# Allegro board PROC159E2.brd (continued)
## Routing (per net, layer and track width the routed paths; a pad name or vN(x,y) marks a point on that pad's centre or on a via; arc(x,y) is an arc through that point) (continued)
OSPI_DQ5: length 22.5
  TOP w0.147: R456.2 v1(30.48,48.63)
  L03_SIG1 w0.091: v1(38.29,38.32) 38.96,39 38.96,43.12 38.96,43.97 38.61,44.32 37.87,44.32 37.43,43.87 36.38,43.87 35.43,44.82 31.49,44.82 30.48,45.84 30.48,46.77 30.56,46.85 30.85,46.85 30.93,46.93 30.93,47.04 30.85,47.12 30.56,47.12 30.48,47.2 30.48,47.32 30.56,47.4 30.85,47.4 30.93,47.48 30.93,47.59 30.85,47.67 30.56,47.67 30.48,47.75 v1(30.48,48.63)
  BOTTOM w0.147: v1(30.48,48.63) 30.63,48.63 30.65,48.61 R105.1 ; U80.26 v1(38.29,38.32)
OSPI_DQ6: length 22.5
  TOP w0.147: v1(33.93,49.36) 33.85,49.28 R457.2
  L03_SIG1 w0.091: v1(38.29,37.32) 39.24,38.27 39.24,42.55 39.24,44.08 38.73,44.59 38.5,44.59 37.76,44.59 37.6,44.43 37.39,44.22 36.49,44.22 34.23,46.49 34.23,48.25 34.1,48.37 33.93,48.37 33.81,48.25 33.81,47.08 33.68,46.95 33.5,46.95 33.38,47.06 33.38,48.81 v1(33.93,49.36)
  BOTTOM w0.147: v1(33.93,49.36) 33.93,49.31 33.99,49.25 R106.1 ; U80.24 v1(38.29,37.32)
OSPI_DQ7: length 23.3
  TOP w0.147: R458.2 v1(37.08,46.22)
  L03_SIG1 w0.091: v1(37.08,46.22) 37.08,46.59 37.06,46.6 37.06,48.41 37.15,48.5 37.28,48.5 37.39,48.4 37.39,46.8 37.6,46.59 37.75,46.59 37.83,46.67 37.83,48.45 37.91,48.53 38.03,48.53 38.11,48.45 38.11,46.68 38.2,46.59 38.73,46.59 39.79,45.52 39.79,44.72 39.51,44.44 39.51,37.55 v1(38.29,36.32)
  BOTTOM w0.147: v1(37.08,46.22) 37.06,46.2 R107.1 ; U80.22 v1(38.29,36.32)
OSPI_DQS_SOC: length 18.4
  L03_SIG1 w0.091: v1(30.26,43.16) 29.85,42.75 29.85,39.25 34.23,34.88 v1(40.73,34.88)
  BOTTOM w0.147: U80.20 v1(40.73,34.88) ; R112.2 v1(30.26,43.16)
OSPI_ERR#: length 43.9
  TOP w0.147: R3865.2 48.56,46.27 v1(48.52,46.32) ; U19.A5 R108.1 27.49,40.15 27.75,39.89 v1(28.01,39.89)
  L03_SIG1 w0.091: v1(48.52,46.32) 48.03,46.8 47.34,46.8 47.06,46.52 47.06,44.69 48.01,43.74 48.82,43.74 49.29,43.27 49.29,38.62 48.94,38.27 48.94,34.7 48.1,33.87 32.66,33.87 29.5,37.03 29.5,38.4 v1(28.01,39.89)
OSPI_LBCLK: length 22.2
  L03_SIG1 w0.091: v1(29.21,42.66) 28.82,42.27 28.82,39.62 33.99,34.45 41.3,34.45 v1(41.73,34.88)
  BOTTOM w0.147: R114.2 29.91,44.18 29.21,43.47 v1(29.21,42.66) ; U80.18 v1(41.73,34.88)
OSPI_RSTN: length 9.2
  TOP w0.147: U19.A4 30.85,39.31 30.98,39.18 v1(30.98,38.72)
  BOTTOM w0.147: U21.4 R121.1 35.68,38.2 35.16,38.72 v1(30.98,38.72)
PMIC_COMP1_IN+: length 45.9
  TOP w0.147: v1(109.12,34.27) 108.79,34.59 108.79,35.08 107.69,36.18 U7.21 ; v1(110.49,5.58) 110.92,5.14 110.92,4.36 110.44,3.88 J15.175
  L03_SIG1 w0.091: v1(110.49,5.58) 111.19,6.28 111.19,7.96 110.11,9.04 106.01,9.04 104.31,10.73 104.31,15.5 105.66,16.84 105.66,21.8 104.3,23.15 104.3,26.18 105.49,27.37 107.65,27.37 108.75,28.47 108.75,33.9 v1(109.12,34.27)
PMIC_COMP1_IN-: length 48.6
  TOP w0.147: v1(110.49,6.59) 111.24,5.84 J15.177 ; v1(110.89,34.34) 110.57,34.66 110.57,35.42 109.19,36.79 U7.24
  L03_SIG1 w0.091: v1(110.89,34.34) 110.41,34.82 109,34.82 108.51,34.33 108.51,28.71 107.53,27.73 105.45,27.73 103.86,26.14 103.86,23.07 105.47,21.46 105.47,18.31 104.02,16.86 104.02,10.66 106,8.68 110.09,8.68 110.93,7.84 110.93,7.04 v1(110.49,6.59)
PMIC_COMP2_IN+: length 56.7
  TOP w0.147: v1(108.23,47.1) 107.69,46.57 U7.28 ; J15.171 v1(108.84,4.56)
  L03_SIG1 w0.091: v1(108.84,4.56) 108.41,4.13 105.46,4.13 104.73,4.86 104.73,7 102.32,9.41 102.32,19.06 101.59,19.79 101.59,26.94 101.14,27.38 101.14,36.92 102.93,38.71 102.93,43.26 104.3,44.64 105.76,44.64 v1(108.23,47.1)
PMIC_COMP2_IN-: length 55.7
  TOP w0.147: v1(109.15,46.04) 109.19,45.99 U7.25 ; v1(110.49,7.61) 109.98,7.1 109.98,6.03 109.64,5.69 J15.173
  L03_SIG1 w0.091: v1(109.15,46.04) 106.99,43.89 106.99,38.83 106.4,38.24 104.51,38.24 102.86,36.59 102.86,35.13 101.81,34.08 101.81,28.46 103.53,26.74 103.53,22.85 104.5,21.88 104.5,18.02 103.75,17.27 103.75,10.58 105.97,8.36 109.74,8.36 v1(110.49,7.61)
PMIC_DIAG_OUT: length 79.1
  TOP w0.147: U1.V4 v1(55.38,32.83) ; U7.32 v1(105.69,46.09)
  L08_SIG2 w0.091: v1(100.32,25.79) 100.32,28.92 102.28,30.87 102.81,30.87 105.2,33.26 105.2,34.1 106.17,35.07 106.17,36.91 105.98,37.1 105.98,43.67 105.69,43.96 v1(105.69,46.09)
  BOTTOM w0.147: v1(100.32,25.79) 99.73,25.19 98.88,25.19 98.29,25.79 95.11,25.79 94.66,25.34 88.91,25.34 87.09,23.51 68.86,23.51 66.93,25.44 66.93,27.57 65.7,28.79 55.49,28.79 54.98,29.31 54.98,31.94 55.38,32.35 v1(55.38,32.83)
PMIC_EN_OUT: length 26.1
  TOP w0.147: U7.17 105.69,36.24 v1(105.74,36.19)
  L08_SIG2 w0.091: v1(105.74,36.19) 103.65,38.29 99.25,38.29 98.23,39.31 98.23,48.3 v1(97.62,48.91)
  BOTTOM w0.147: v1(97.62,48.91) 94.11,52.43 R51.1
PMIC_INTN: length 62.3
  TOP w0.147: U7.22 108.19,36.4 109.3,35.3 109.3,34.93 v1(109.92,34.3) ; U1.R17 v1(66.58,35.23)
  L03_SIG1 w0.091: v1(109.92,34.3) 109.03,33.4 109.03,28.37 107.35,26.69 v1(106.44,26.69)
  BOTTOM w0.114: v1(66.58,35.23) 66.18,34.83 66.18,33.36
  BOTTOM w0.147: v1(106.44,26.69) 88.18,26.69 87.75,26.25 68.22,26.25 67.49,26.99 67.49,28.63 66.18,29.93 66.18,33.36
PMIC_NRST: length 23.7
  TOP w0.147: U7.13 103.69,36.5 103.94,36.25 103.94,36.25 v1(104.26,35.93) ; v1(94.37,38.36) 93.54,37.53 84.93,37.53 84.05,36.65 R432.1
  L08_SIG2 w0.091: v1(104.26,35.93) 102.64,37.55 97.87,37.55 97.05,38.36 v1(94.37,38.36)
PMIC_SAFE_OUT1: length 109.2
  TOP w0.147: v1(66.24,6.59) 65.44,5.79 J15.113
  L08_SIG2 w0.091: v1(66.24,6.59) 66.84,6.59 69.11,8.86 69.11,12.12 70.33,13.34 90.56,13.34 90.99,12.91 90.99,12.39 94.5,8.88 94.5,6.17 95.61,5.06 104.4,5.06 105.93,3.53 108.92,3.53 109.64,4.25 109.64,8.09 108.22,9.51 108.22,10.02 107.19,11.05 104.76,11.05 104.28,11.53 104.28,15.36 103.91,15.74 103.91,17.49 104.53,18.12 104.53,24.11 104.06,24.58 104.06,25.85 105.8,27.59 105.8,30.46 108.44,33.09 108.44,35.76 109.79,37.11 v1(109.79,45.36)
  BOTTOM w0.147: v1(109.79,45.36) 109.24,45.36 108.81,44.94 R32.1
PMIC_SAFE_OUT2: length 80.4
  TOP w0.147: Q5.1 92.8,39.3 92.81,39.29 R202.1 94.07,39.96 95.78,41.67 95.78,46.58 97.24,48.04 97.67,48.04 98.51,48.88 v1(99.06,48.88) ; U7.27 v1(108.19,46.09)
  L03_SIG1 w0.091: v1(110.31,4.56) 109.76,5.11 109.76,5.37 109.05,6.08 105.36,6.08 105,6.44 105,7.03 102.56,9.46 102.56,18.73 102.8,18.97 102.8,20.84 103.06,21.1 103.06,26.75 101.44,28.37 101.44,36.35 103.89,38.8 103.89,43.21 104.94,44.26 106.36,44.26 v1(108.19,46.09)
  L08_SIG2 w0.091: v1(99.06,48.88) 101.53,48.88 102.25,48.16 106.77,48.16 107.62,47.31 107.62,46.66 v1(108.19,46.09)
  BOTTOM w0.147: v1(110.31,4.56) 110.63,4.24 110.86,4.24 111.24,3.86 J15.178
PMIC_SPI1_CLK: length 100.6
  TOP w0.147: v1(106.62,10.06) 106.09,9.53 105.48,9.53 105.13,9.88 102.87,9.88 102.5,9.51 95.12,9.51 92.52,12.11 90.2,12.11 89.86,12.46 89.86,13.12 88.94,14.04 65.18,14.04 64.51,14.71 62.35,14.71 60.61,12.97 U8.2 ; v1(104.77,47.1) 105.19,46.68 U7.33
  L08_SIG2 w0.091: v1(106.62,10.06) 106.09,10.59 104.62,10.59 103.77,11.44 103.77,12.29 100.56,15.5 100.56,23.83 103.59,26.86 103.59,29.61 107.3,33.32 107.3,34.62 107.67,34.99 107.67,38.27 108.01,38.61 108.01,44.31 106.69,45.63 106.69,47.02 106.12,47.59 105.26,47.59 v1(104.77,47.1)
  BOTTOM w0.147: R41.2 104.77,47.34 v1(104.77,47.1)
PMIC_SPI1_CS0: length 97
  TOP w0.147: v1(103.75,46.08) 103.69,46.03 U7.36 ; U8.14 61.26,16.06 62.1,15.23 64.64,15.23 65.51,14.36 89.16,14.36 90.11,13.4 91.79,13.4 95.32,9.87 102.3,9.87 102.8,10.38 105.39,10.38 v1(105.71,10.06)
  L08_SIG2 w0.091: v1(103.75,46.08) 104.24,46.58 105.87,46.58 106.27,46.17 106.27,44.95 107,44.22 107,38.58 107.36,38.22 107.36,35.39 106.18,34.21 106.18,32.62 103.4,29.84 102.8,29.84 102.14,29.18 102.14,26.05 100.38,24.29 100.38,15.3 103.5,12.18 103.5,11.3 104.48,10.32 105.45,10.32 v1(105.71,10.06)
  BOTTOM w0.147: v1(103.75,46.08) 103.3,46.08 102.99,46.39 R39.2
PMIC_SPI1_D0: length 113.3
  TOP w0.147: U7.35 104.19,45.92 104.22,45.94 104.22,46.64 v1(103.75,47.1) ; v1(107.72,54.19) TP17.1 109.08,54.19 109.11,54.22 R40.2 ; U8.5 62.56,13.53 63.27,14.24 64.38,14.24 64.89,13.73 88.69,13.73 89.5,12.92 89.5,12.28 90.02,11.75 92.37,11.75 94.99,9.13 102.71,9.13 103.1,9.52 104.88,9.52 105.29,9.12 106.6,9.12 v1(107.54,10.06)
  L03_SIG1 w0.091: v1(103.75,47.1) 104.52,47.87 104.52,49.1 107.72,52.31 v1(107.72,54.19)
  L08_SIG2 w0.091: v1(107.54,10.06) 106.76,10.83 104.63,10.83 104.05,11.42 104.05,12.39 100.74,15.69 100.74,23.57 104.76,27.59 104.76,30.41 107.21,32.86 107.75,32.86 108.23,33.34 108.23,36.99 109.4,38.16 109.4,43.9 107.07,46.23 107.07,47.17 106.37,47.87 104.52,47.87 v1(103.75,47.1)
PMIC_SPI1_D1: length 81.8
  TOP w0.147: v1(63.37,19.93) 63.37,19.47 63.21,19.31 U8.11
  L08_SIG2 w0.091: v1(109.35,55.35) 109.35,52.67 110.91,51.11 110.91,37.09 108.69,34.87 108.69,32.71 106.16,30.18 106.16,27.19 v1(104.86,25.88)
  BOTTOM w0.147: v1(109.35,55.35) R38.2 R142.2 ; v1(104.86,25.88) 101.26,25.88 100.14,24.76 98.59,24.76 98.03,25.32 95.72,25.32 94.78,24.38 88.81,24.38 87.5,23.08 67.69,23.08 65.55,20.94 64.38,20.94 v1(63.37,19.93)
PMIC_WKUP1: length 66.9
  TOP w0.147: v1(100.22,36.06) 100.19,36.08 U7.6
  L03_SIG1 w0.091: v1(66.24,7.61) 66.24,8.83 66.95,9.54 66.95,10.49 70.75,14.29 71.94,14.29 75.93,18.28 75.93,24.63 v1(74.81,25.76)
  L08_SIG2 w0.091: v1(100.22,36.06) 99.83,35.67 99.83,26.31 v1(99.31,25.79)
  BOTTOM w0.147: J15.114 65.44,6.81 v1(66.24,7.61) ; v1(74.81,25.76) 75.26,25.76 75.4,25.62 R34.2 76.88,24.91 77.64,25.67 88.37,25.67 88.94,26.23 98.86,26.23 v1(99.31,25.79)
PMIC_WKUP2: length 102.1
  TOP w0.147: v1(108.84,5.58) 109.39,6.13 109.39,7.89 108.03,9.26 108.03,10.23 107.4,10.86 94.87,10.86 91.98,13.75 90.31,13.75 89.34,14.72 79.65,14.72 75.91,18.46 J22.1 ; v1(98.67,47.87) 99.04,47.5 99.2,47.5 100.06,46.64 100.06,46.1 100.19,45.97 U7.43
  L03_SIG1 w0.091: v1(108.84,5.58) 109.26,5.15 109.26,4.38 108.83,3.95 105.38,3.95 104.55,4.79 104.55,6.93 102.13,9.34 102.13,18.88 101.34,19.68 101.34,26.74 100.73,27.35 100.73,36.65 99.9,37.48 99.9,46.64 v1(98.67,47.87)
  BOTTOM w0.147: v1(108.84,5.58) 108.38,5.12 108.38,4.37 108.84,3.92 J15.172
PORZ: length 259.1
  TOP w0.147: R419.1 67.93,11.93 v1(67.81,12.05) ; U36.2 v1(80.76,39.79) ; v1(86.22,36.38) 86.9,35.71 86.9,33.83 86.62,33.55 86.62,29.22 86.39,28.99 U79.4 84.79,28.3 TP75.1 v1(82.09,26.84) 81.12,25.87 75.79,25.87 73.3,23.37 67.11,23.37 66.56,22.83 62.05,22.83 61.25,22.02 50.98,22.02 47.56,25.44 41.12,25.44 40.3,26.25 39.32,26.25 38.37,27.2 38.37,31.12 v1(37.19,32.3) 35.52,33.97 27.87,33.97 26.8,32.9 24.39,32.9 21.91,35.37 21.91,52.66 25.77,56.51 25.77,60.89 27.7,62.82 27.7,63.65 26.9,64.45 26.9,66.67 28.66,68.43 41.14,68.43 45.95,73.24 45.95,74.38 46.62,75.05 46.62,77.77 45.75,78.64 45.75,85.2 48.86,88.3 51.67,88.3 53.96,90.6 55.11,90.6 56.69,92.18 v1(57.4,92.18) 57.4,91.1 58.2,90.3 61.94,90.3 63.55,91.91 67.18,91.91 67.54,92.26 67.54,99.86 v1(68,100.32) ; U1.R2 v1(53.78,35.23)
  L08_SIG2 w0.091: v1(37.19,32.3) 40.77,32.3 41.81,33.34 48.54,33.34 49.9,34.7 52.64,34.7 53.17,35.23 v1(53.78,35.23) ; v1(82.09,26.84) 82.09,20.03 76.06,14 69.76,14 v1(67.81,12.05)
  BOTTOM w0.147: U21.2 32.61,36.27 32.98,35.9 32.98,34.67 33.38,34.26 36.3,34.26 37.19,33.38 v1(37.19,32.3) ; R187.1 52.92,34.25 53.4,34.72 53.4,34.85 v1(53.78,35.23) ; v1(86.22,36.38) 82.11,36.38 81.21,35.48 80.59,35.48 80.05,36.01 80.05,39.08 v1(80.76,39.79) ; R327.1 v1(57.4,92.18) ; v1(68,100.32) U39.2
PORZ_RST: length 159
  TOP w0.147: U78.3 v1(80.19,32.03)
  L03_SIG1 w0.091: v1(52.9,98.23) 57.06,102.39 67.17,102.39 67.89,103.11 70.47,103.11 71.4,102.18 75.29,102.18 81.23,108.12 100.4,108.12 104.95,103.58 v1(104.95,97.59)
  L08_SIG2 w0.091: v1(96.61,48.91) 95.56,49.96 95.56,65.63 94.82,66.37 94.82,72.52 90.72,76.63 90.72,77.55 90.99,77.82 91.94,77.82 92.27,77.49 99.94,77.49 105.78,83.33 105.78,96.75 v1(104.95,97.59)
  BOTTOM w0.147: v1(96.61,48.91) 86.81,39.11 86.81,36.2 86.44,35.84 83.08,35.84 82.03,34.79 82.03,32.95 81.11,32.03 v1(80.19,32.03) ; v1(52.9,98.23) R427.2 52.9,95.25 53.06,95.09 U76.7
PORZ_VMAIN: length 1.8
  TOP w0.147: U78.4 U79.1
PR0_IEP0_EDC_SYNC_OUT0: length 2
  TOP w0.147: R420.1 J16.1
PR0_IEP0_EDC_SYNC_OUT1: length 10.4
  TOP w0.147: J18.1 64.28,54.88 64.28,53.79 63.82,53.34 R422.1
PR0_IEP0_EDIO_DATA_IN_OUT30: length 12.5
  BOTTOM w0.147: J17.1 62.08,63.67 62.08,56.52 63.68,54.92 R421.1
PR0_IEP0_EDIO_DATA_IN_OUT31: length 2.4
  TOP w0.147: J19.1 67.96,18.09 68.45,17.61 R423.1
PR0_MDIO0_MDC: length 21.2
  TOP w0.147: v1(74.47,36.71) 73.96,37.22 R211.2 ; R470.2 v1(77.35,29.38)
  L03_SIG1 w0.091: v1(77.35,29.38) 76.64,30.09 76.64,36.27 74.72,38.2 74.25,38.2 73.86,37.81 73.86,37.31 v1(74.47,36.71)
  BOTTOM w0.147: U90.2 77.9,37.43 77.5,37.83 75.59,37.83 v1(74.47,36.71) ; R470.2 v1(77.35,29.38)
PR0_MDIO0_MDC_ADD: length 87.7
  TOP w0.147: v1(71.53,91.19) 71.79,91.44 J8.20
  L08_SIG2 w0.091: v1(71.53,91.19) 71.53,86.48 70.3,85.25 70.3,84.71 69.93,84.34 68.38,84.34 67.43,83.4 67.43,80.65 v1(68.28,79.8)
  BOTTOM w0.147: v1(68.28,79.8) 67.81,79.32 65.42,79.32 64.64,80.11 63.8,80.11 62.45,78.75 62.45,72.01 60.9,70.46 60.9,67.65 61.6,66.95 64.98,66.95 65.35,66.58 65.35,64.17 63.32,62.14 63.32,57.15 68.02,52.45 71.09,52.45 72.03,51.52 72.03,49.78 71.78,49.53 71.78,48.12 71.96,47.95 72.29,47.62 74.39,47.62 74.85,47.16 76.07,47.16 76.59,46.64 76.59,45.55 75.75,44.7 75.75,41.18 73.39,38.82 73.39,34.96 74.23,34.12 75.1,34.12 75.37,34.4 R3867.2 76.77,34.96 76.9,35.09 U90.4
PR0_MDIO0_MDC_ON: length 62.9
  L08_SIG2 w0.091: v1(86.22,35.29) 90.53,39.6 90.53,47.64 92.47,49.58 92.47,57.71 93.06,58.3 93.06,62.31 91.35,64.02 91.35,73.72 89.92,75.15 v1(89.53,75.15)
  BOTTOM w0.147: U35.42 88.92,73.64 89.53,74.25 v1(89.53,75.15) ; U81.4 77.14,28.38 77.7,28.94 R472.2 83.76,28.94 85.41,30.6 85.41,33.72 85.7,34 85.7,34.76 v1(86.22,35.29)
PR0_MDIO0_MDIO: length 20.9
  TOP w0.147: R208.2 v1(74.47,34.7) ; v1(70.59,28.88) 71.34,28.88 71.74,28.48 R471.2
  L03_SIG1 w0.091: v1(74.47,34.7) 74.91,34.26 74.91,32.68 73.51,31.28 72.98,31.28 v1(70.59,28.88)
  BOTTOM w0.147: U90.8 77.4,38.96 76.84,38.4 74.45,38.4 73.81,37.76 73.81,35.36 v1(74.47,34.7) ; U81.8 v1(70.59,28.88)
PR0_MDIO0_MDIO_ADD: length 78.2
  TOP w0.147: J8.22 v1(73.27,91.84)
  L08_SIG2 w0.091: v1(68.28,78.89) 68.73,79.34 68.73,79.99 67.63,81.09 67.63,83.32 68.33,84.02 70.9,84.02 71.96,85.08 71.96,90.53 v1(73.27,91.84)
  BOTTOM w0.147: U90.6 R3866.2 76.99,42.07 77.19,42.26 77.19,46.46 76.19,47.45 74.98,47.45 74.52,47.91 72.41,47.91 72.2,48.12 72.2,49.47 72.32,49.59 72.32,51.64 71.21,52.75 68.14,52.75 63.61,57.27 63.61,62.02 65.65,64.05 65.65,66.7 65.1,67.25 61.72,67.25 61.2,67.77 61.2,70.34 62.74,71.89 62.74,78.63 63.79,79.68 64.51,79.68 65.3,78.89 v1(68.28,78.89)
PR0_MDIO0_MDIO_ON: length 75
  L08_SIG2 w0.091: v1(86.22,34.32) 85.78,34.77 85.78,36.92 90.29,41.43 90.29,47.75 92.22,49.68 92.22,57.81 92.81,58.4 92.81,61.19 90.31,63.69 90.31,65.16 90.93,65.79 90.93,73.5 90.16,74.28 89.63,74.28 v1(88.36,73.01)
  BOTTOM w0.147: v1(86.22,34.32) 86.78,34.32 87.7,33.4 87.7,29.11 86.39,27.79 78.54,27.79 77.47,26.72 70.33,26.72 70.15,26.9 R473.2 70.55,27.88 U81.6 ; v1(88.36,73.01) 88.42,72.95 U35.41
PR0_PRU0_GPIO0: length 35.3
  TOP w0.147: U87.2 v1(79.01,56.89) ; U1.K17 v1(66.58,39.23)
  L03_SIG1 w0.091: v1(66.58,39.23) 67.03,38.78 69.26,38.78 69.63,39.16 72.65,39.16 73.18,39.69 73.83,39.69 79.68,45.54 79.68,50.46 80.93,51.71 80.93,58.12 80.67,58.38 80.37,58.38 80.22,58.24 80.22,57.69 80.12,57.59 79.83,57.59 79.72,57.7 79.72,58.25 79.59,58.38 79.17,58.38 79.01,58.23 v1(79.01,56.89)
PR0_PRU0_GPIO1: length 35.2
  TOP w0.147: U87.3 79.2,57.39 79.74,56.86 v1(79.74,56.45) ; U1.K18 v1(67.38,39.23)
  L03_SIG1 w0.091: v1(79.74,56.45) 80.58,55.61 80.58,51.75 79.41,50.57 79.41,45.88 78.75,45.22 78.6,45.22 78.31,45.51 78.16,45.51 78.05,45.4 78.05,45.25 78.34,44.96 78.34,44.81 78.23,44.71 78.08,44.71 77.79,44.99 77.64,44.99 77.54,44.88 77.54,44.73 77.82,44.45 77.82,44.29 77.71,44.19 77.56,44.19 77.28,44.47 77.12,44.47 77.02,44.36 77.02,44.21 77.3,43.93 77.3,43.78 76.46,42.93 76.31,42.93 76.13,43.11 75.98,43.11 75.88,43 75.88,42.85 76.05,42.68 76.05,42.52 75.94,42.42 75.79,42.42 75.62,42.59 75.46,42.59 75.36,42.48 75.36,42.33 75.53,42.16 75.53,42.01 75.42,41.9 75.27,41.9 75.1,42.07 74.95,42.07 74.84,41.97 74.84,41.81 75.01,41.64 75.01,41.49 74.91,41.38 74.75,41.38 74.58,41.56 74.43,41.56 74.32,41.45 74.32,41.3 74.5,41.12 74.5,40.97 74.39,40.87 74.24,40.87 74.06,41.04 73.91,41.04 73.81,40.93 73.81,40.78 73.98,40.61 73.98,40.45 73.71,40.18 70.12,40.18 69.17,39.23 v1(67.38,39.23)
PR0_PRU0_GPIO2: length 35.3
  TOP w0.147: U1.J18 v1(67.38,40.83) ; v1(79.27,54.97) 80.19,55.9 80.19,57 79.3,57.89 U87.4
  L03_SIG1 w0.091: v1(79.27,54.97) 78.3,54.01 78.3,53.58 78.19,53.47 77.44,53.47 77.33,53.36 77.33,53.21 77.43,53.1 78.19,53.1 78.3,53 78.3,52.84 78.19,52.74 77.44,52.74 77.33,52.63 77.33,52.48 77.43,52.37 78.19,52.37 78.53,52.03 78.53,49.29 78.02,48.78 77.44,48.78 77.2,49.02 77.2,50.89 77,51.09 76.71,51.09 76.47,50.85 76.47,47.84 75.62,46.98 75.47,46.98 75.19,47.26 75.04,47.26 74.93,47.15 74.93,47 75.21,46.73 75.21,46.57 74.45,45.82 73.86,45.82 68.87,40.83 v1(67.38,40.83)
PR0_PRU0_GPIO3: length 35.1
  TOP w0.147: v1(78.14,55.11) 78.79,54.46 79.4,54.46 80.52,55.57 80.52,57.56 79.69,58.39 U87.5 ; U1.J17 v1(66.58,40.83)
  L03_SIG1 w0.091: v1(66.58,40.83) 66.81,40.83 67.2,41.22 67.52,41.22 69.94,43.63 70.4,43.63 73.03,46.26 74.11,46.26 74.58,46.73 74.58,47.84 74.86,48.13 74.86,48.28 74.48,48.66 74.48,48.81 74.58,48.92 74.74,48.92 75.12,48.54 75.27,48.54 75.38,48.64 75.38,48.79 74.99,49.18 74.99,49.33 75.1,49.44 75.25,49.44 75.63,49.05 75.79,49.05 76.09,49.36 76.09,49.9 75.99,50.01 75.58,50.01 75.47,50.12 75.47,50.27 75.58,50.38 75.99,50.38 76.09,50.48 76.09,51.47 75.99,51.58 75.42,51.58 75.31,51.68 75.31,51.84 75.42,51.94 75.99,51.94 76.09,52.05 76.09,52.2 75.99,52.31 75.42,52.31 75.31,52.42 75.31,52.57 75.42,52.67 75.99,52.67 76.09,52.78 76.09,53.6 77.6,55.11 v1(78.14,55.11)
PR0_PRU0_GPIO4: length 35.2
  TOP w0.147: U87.6 v1(79.01,58.89) ; U1.K16 v1(65.78,39.23)
  L03_SIG1 w0.091: v1(65.78,39.23) 66.28,39.73 67.76,39.73 68.19,40.16 69.28,40.16 72.84,43.72 75.03,43.72 75.33,44.02 75.33,44.17 75.17,44.33 75.17,44.48 75.28,44.59 75.43,44.59 75.59,44.43 75.74,44.43 75.85,44.54 75.85,44.69 75.69,44.84 75.69,45 75.8,45.1 75.95,45.1 76.1,44.95 76.26,44.95 76.36,45.06 76.36,45.21 76.21,45.36 76.21,45.51 76.32,45.62 76.47,45.62 76.62,45.47 76.77,45.47 76.88,45.57 76.88,45.72 76.73,45.88 76.73,46.03 76.83,46.14 76.99,46.14 77.14,45.98 77.29,45.98 77.4,46.09 77.4,46.24 77.24,46.4 77.24,46.55 77.35,46.65 77.5,46.65 77.66,46.5 77.81,46.5 77.92,46.61 77.92,46.76 77.76,46.91 77.76,47.06 77.87,47.17 78.02,47.17 78.17,47.02 78.33,47.02 78.43,47.12 78.43,47.28 78.28,47.43 78.28,47.58 78.39,47.69 78.54,47.69 78.69,47.53 78.84,47.53 79.13,47.82 79.13,50.69 80.31,51.87 80.31,55.26 79.15,56.41 78.84,56.41 78.57,56.68 78.57,58.45 v1(79.01,58.89)
PR0_PRU0_GPIO5: length 35.6
  TOP w0.147: v1(79.93,58.89) 79.43,59.39 U87.7 ; U1.G17 v1(66.58,42.43)
  L03_SIG1 w0.091: v1(79.93,58.89) 80.57,59.54 80.57,61.17 80.36,61.38 80.36,62.14 80.12,62.38 79.8,62.38 79.44,62.74 79.44,63.16 79.22,63.38 78.81,63.38 78.45,63.02 78.45,62.78 77.83,62.15 77.83,60.19 77.4,59.76 75.49,59.76 75.21,59.48 75.21,54.52 73.48,52.79 73.48,50.83 71.4,48.75 71.4,47.25 v1(66.58,42.43)
PR0_PRU0_GPIO6: length 35.5
  TOP w0.147: v1(79.93,61.89) 79.43,61.39 U87.11 ; U1.K15 v1(64.98,39.23)
  L03_SIG1 w0.091: v1(79.93,61.89) 79.46,61.42 79.46,60.4 78.85,59.8 78.85,59.35 78.3,58.8 78.3,55.94 78.8,55.44 79.47,55.44 79.74,55.17 79.74,51.68 78.86,50.8 78.86,48.85 74,43.99 72.65,43.99 69.1,40.44 68.08,40.44 67.64,40 65.75,40 v1(64.98,39.23)
PR0_PRU0_GPIO8: length 35.1
  TOP w0.147: U1.G15 v1(64.98,42.43) ; U87.12 v1(79.01,61.89)
  L03_SIG1 w0.091: v1(64.98,42.43) 65.38,42.83 65.96,42.83 66.19,42.59 66.19,42.25 66.42,42.02 67.57,42.02 69.77,44.21 70.49,44.21 71.04,44.76 71.04,44.92 70.66,45.3 70.66,45.45 70.77,45.56 70.92,45.56 71.3,45.17 71.45,45.17 71.56,45.28 71.56,45.43 71.18,45.82 71.18,45.97 71.28,46.08 71.43,46.08 71.82,45.69 71.97,45.69 72.08,45.8 72.08,45.95 71.69,46.34 71.69,46.49 71.8,46.6 71.95,46.6 72.34,46.21 72.49,46.21 72.6,46.32 72.6,46.47 72.21,46.85 72.21,47.01 72.32,47.11 72.47,47.11 72.86,46.73 73.01,46.73 73.7,47.42 73.7,47.86 73.32,48.23 73.32,49.19 74.89,50.76 74.89,52.81 78.02,55.94 78.02,58.99 78.51,59.47 78.51,61.39 v1(79.01,61.89)
PR0_PRU0_GPIO9: length 30.9
  TOP w0.147: U1.F17 v1(66.58,43.23) ; v1(79.93,62.89) 79.43,62.39 U87.13
  L03_SIG1 w0.091: v1(66.58,43.23) 68.78,45.43 68.78,47.81 72.1,51.13 72.1,52.01 74.93,54.84 74.93,61.64 75.41,62.11 77.36,62.11 78.03,62.78 78.03,62.99 78.7,63.66 79.54,63.66 79.93,63.27 v1(79.93,62.89)
PR0_PRU0_GPIO10: length 26.7
  TOP w0.147: U1.G18 v1(67.38,42.43) ; U87.14 v1(79.01,62.89)
  L03_SIG1 w0.091: v1(79.01,62.89) 78.17,62.05 78.17,59.92 77.75,59.51 77.75,56.33 73.93,52.51 73.93,50.7 71.75,48.52 71.75,47.17 67.38,42.8 v1(67.38,42.43)
PR0_PRU0_GPIO11: length 79.9
  TOP w0.147: U1.M16 v1(65.78,37.63)
  L03_SIG1 w0.091: v1(80.39,99.84) 79.96,99.84 77.32,97.19 77.32,80.14 73.1,75.92 73.1,74.03 69.23,70.16 66.4,70.16 62.4,66.16 62.4,63.28 61.63,62.51 61.63,53.64 60.86,52.87 60.86,47.29 60.58,47.01 60.58,40.46 61.35,39.69 62.76,39.69 62.97,39.48 62.97,37.42 63.16,37.23 65.38,37.23 v1(65.78,37.63)
  BOTTOM w0.147: U88.4 80.89,99.34 v1(80.39,99.84)
PR0_PRU0_GPIO12: length 79.7
  TOP w0.147: U1.M15 v1(64.98,37.63)
  L03_SIG1 w0.091: v1(64.98,37.63) 64.58,38.03 64.03,38.03 63.79,38.27 63.79,39.43 63.31,39.92 62.08,39.92 61.38,40.62 61.38,48.94 62.74,50.3 62.74,50.45 62.54,50.65 62.54,50.8 62.65,50.91 62.8,50.91 63,50.71 63.15,50.71 63.26,50.82 63.26,50.97 63.06,51.17 63.06,51.32 63.17,51.43 63.32,51.43 63.52,51.23 63.67,51.23 64.02,51.58 64.02,52.4 61.91,54.52 61.91,62.4 62.67,63.16 62.67,66.05 66.51,69.88 69.28,69.88 73.37,73.97 73.37,75.84 77.59,80.06 77.59,96.84 80.09,99.34 80.81,99.34 v1(81.3,99.84)
  BOTTOM w0.147: U88.5 v1(81.3,99.84)
PR0_PRU0_GPIO13: length 80
  TOP w0.147: U1.H17 v1(66.58,41.63)
  L03_SIG1 w0.091: v1(66.58,41.63) 66.41,41.63 66.02,41.24 64.02,41.24 63.78,41.48 63.78,47.64 64.41,48.27 66.4,48.27 66.89,48.75 66.89,52.04 62.71,56.21 62.71,61.46 65.46,64.21 65.46,64.97 74.1,73.61 74.1,75.37 75.35,76.62 76.62,76.62 77.19,77.18 78.57,77.18 78.69,77.31 78.69,93.33 80.04,94.68 80.04,96.58 80.65,97.19 81.34,97.19 81.94,97.78 81.94,99.89 81.48,100.34 80.88,100.34 v1(80.39,100.84)
  BOTTOM w0.147: v1(80.39,100.84) 80.89,100.34 U88.6
PR0_PRU0_GPIO14: length 80.3
  TOP w0.147: U1.H16 v1(65.78,41.63)
  L03_SIG1 w0.091: v1(65.78,41.63) 65.39,42.02 64.84,42.02 64.59,42.27 64.59,47.57 64.93,47.9 65.96,47.9 66.28,47.58 66.28,45.68 66.43,45.53 66.64,45.53 66.78,45.67 66.78,47.48 67.18,47.87 67.18,52.16 63,56.33 63,61.36 65.74,64.1 65.74,64.86 74.31,73.43 74.31,75.13 75.39,76.21 78.53,76.21 78.92,76.61 78.92,93.11 80.34,94.53 80.34,96.18 81.03,96.87 81.41,96.87 82.21,97.67 82.21,100.3 81.67,100.84 v1(81.3,100.84)
  BOTTOM w0.147: U88.7 v1(81.3,100.84)
PR0_PRU0_GPIO15: length 79.9
  TOP w0.147: U1.L16 v1(65.78,38.43)
  L03_SIG1 w0.091: v1(65.78,38.43) 65.39,38.82 64.79,38.82 64.59,39.02 64.59,39.67 64.05,40.21 62.57,40.21 62.18,40.6 62.18,48.14 62.45,48.42 62.45,48.57 62.1,48.92 62.1,49.08 62.2,49.18 62.36,49.18 62.71,48.83 62.86,48.83 62.97,48.93 62.97,49.08 62.61,49.44 62.61,49.59 62.72,49.7 62.87,49.7 63.23,49.34 63.38,49.34 63.49,49.45 63.49,49.6 63.13,49.96 63.13,50.11 63.24,50.22 63.39,50.22 63.75,49.86 63.9,49.86 64.01,49.97 64.01,50.12 63.65,50.48 63.65,50.63 63.76,50.73 63.91,50.73 64.26,50.38 64.42,50.38 64.58,50.54 64.58,52.23 62.18,54.63 62.18,61.68 64.93,64.43 64.93,65.19 73.61,73.88 73.61,75.66 78.15,80.2 78.15,93.78 79.26,94.89 79.26,97.71 v1(80.39,98.84)
  BOTTOM w0.147: U88.2 80.89,98.34 v1(80.39,98.84)
PR0_PRU0_GPIO16: length 79.7
  TOP w0.147: U1.H18 v1(67.38,41.63)
  L03_SIG1 w0.091: v1(81.3,98.84) 79.62,97.16 79.62,94.78 78.43,93.59 78.43,80.1 73.87,75.55 73.87,73.77 65.19,65.09 65.19,64.32 62.44,61.57 62.44,56.03 65.93,52.54 65.93,50.45 65.69,50.2 65.53,50.2 65.29,50.45 65.14,50.45 65.03,50.34 65.03,50.19 65.28,49.95 65.28,49.79 65.17,49.69 65.02,49.69 64.77,49.93 64.62,49.93 64.52,49.82 64.52,49.67 64.76,49.43 64.76,49.28 64.65,49.17 64.5,49.17 64.26,49.41 64.11,49.41 64,49.31 64,49.16 64.24,48.91 64.24,48.76 64.13,48.65 63.98,48.65 63.74,48.9 63.59,48.9 63.48,48.79 63.48,48.64 63.72,48.39 63.72,48.24 63.62,48.14 63.47,48.14 63.22,48.38 63.07,48.38 62.96,48.27 62.96,48.12 63.21,47.88 63.21,47.73 62.98,47.5 62.98,40.63 63.2,40.41 65.98,40.41 66.18,40.61 66.18,41.06 66.37,41.24 66.8,41.24 66.98,41.42 67.17,41.42 v1(67.38,41.63)
  BOTTOM w0.147: U88.3 v1(81.3,98.84)
PR0_PRU0_REF_CLK: length 118.9
  TOP w0.147: v1(18.79,33.49) 16.39,33.49 16.23,33.65 R272.2
  L03_SIG1 w0.091: v1(43.31,62.87) 41.01,65.17 25.08,65.17 18.79,58.87 v1(18.79,33.49)
  L08_SIG2 w0.091: v1(88.42,64.25) 91.05,61.62 91.05,60.74 86.19,55.87 82.85,55.87 81.34,54.36 71.8,54.36 70.38,55.78 69.29,55.78 68.96,56.11 67.42,56.11 66.63,56.9 66.63,58.11 66.37,58.37 66.02,58.37 65.53,58.87 65.11,58.87 63.61,57.37 54.97,57.37 53.46,58.88 53.46,59.89 50.11,63.24 49.45,63.24 49.08,62.87 v1(43.31,62.87)
  BOTTOM w0.147: U35.20 v1(88.42,64.25)
PR0_PRU1_GPIO0: length 57.5
  BOTTOM w0.147: U89.2 81.67,85.35 81.41,85.08 81.41,84.68 81.99,84.1 81.99,80.65 82.67,79.96 82.67,71.47 81.46,70.25 81.46,65.9 85.82,61.54 85.82,56.17 80.62,50.97 80.62,46.98 81.3,46.3 81.71,46.3 82.19,45.83 82.19,44.98 81.62,44.4 78.59,44.4 78.24,44.76 78.24,49.96 77.93,50.27 R247.2
PR0_PRU1_GPIO1: length 57
  TOP w0.147: v1(78.04,50.79) 77.52,50.27 R248.2
  BOTTOM w0.147: U89.3 81.46,85.85 81.02,85.41 81.02,84.65 81.67,83.99 81.67,80.5 82.35,79.83 82.35,71.61 81.13,70.39 81.13,65.77 85.27,61.63 85.27,56.22 80.33,51.27 80.33,46.59 81.28,45.63 81.28,45.19 80.92,44.83 78.94,44.83 78.67,45.09 78.67,50.16 v1(78.04,50.79)
PR0_PRU1_GPIO2: length 57.6
  TOP w0.147: v1(75.64,51.05) R249.2
  BOTTOM w0.147: v1(75.64,51.05) 75.18,51.05 75,51.23 75,51.74 75.67,52.41 77.42,52.41 79.08,50.75 79.08,46.67 79.26,46.48 79.61,46.48 79.83,46.71 79.83,51.36 84.86,56.4 84.86,61.58 80.81,65.63 80.81,70.52 82.02,71.74 82.02,79.69 81.36,80.35 81.36,83.88 80.61,84.63 80.61,85.5 81.46,86.35 U89.4
PR0_PRU1_GPIO3: length 57.1
  TOP w0.147: v1(81.3,86.85) 82.23,85.92 84.9,85.92 85.35,85.47 85.35,84.86 86.19,84.02 86.19,80.94 87.16,79.96 87.16,79.78 86.84,79.45 86.84,79.27 86.97,79.14 87.15,79.14 87.48,79.47 87.66,79.47 87.79,79.34 87.79,79.15 87.46,78.83 87.46,78.65 87.59,78.52 87.77,78.52 88.1,78.84 88.28,78.84 88.72,78.41 88.72,74.58 87.56,73.42 87.56,71.5 88.37,70.68 88.37,66.04 86.44,64.11 84.31,64.11 83.85,63.65 83.85,63.24 83.98,63.11 84.47,63.11 84.6,62.98 84.6,62.8 84.47,62.67 83.98,62.67 83.85,62.54 83.85,62.36 83.98,62.23 84.47,62.23 84.6,62.1 84.6,61.92 84.47,61.79 83.98,61.79 83.85,61.66 83.85,61.47 83.98,61.35 84.47,61.35 84.6,61.22 84.6,61.03 84.47,60.9 83.98,60.9 83.85,60.77 83.85,60.32 83.12,59.58 83.12,54.83 80,51.71 v1(76.86,51.71)
  BOTTOM w0.147: U89.5 v1(81.3,86.85) ; R250.2 75.76,50.27 76.24,50.74 76.24,51.09 v1(76.86,51.71)
PR0_PRU1_GPIO4: length 57.5
  TOP w0.147: R251.2 v1(74.42,51.05)
  BOTTOM w0.147: v1(74.42,51.05) 74.42,51.88 75.39,52.85 78.27,52.85 78.4,52.73 78.4,52.26 78.53,52.13 78.71,52.13 78.84,52.26 78.84,52.73 78.97,52.85 79.15,52.85 79.28,52.73 79.28,52.26 79.41,52.13 79.59,52.13 79.72,52.26 79.72,52.73 79.85,52.85 80.2,52.85 80.35,53 80.35,53.21 80.17,53.39 80.17,53.58 80.3,53.7 80.48,53.7 80.83,53.36 81.01,53.36 81.14,53.49 81.14,53.67 80.79,54.02 80.79,54.2 80.92,54.33 81.11,54.33 81.45,53.99 81.63,53.99 81.76,54.12 81.76,54.3 81.42,54.64 81.42,54.83 81.55,54.95 81.73,54.95 82.08,54.61 82.26,54.61 82.39,54.74 82.39,54.92 82.04,55.27 82.04,55.45 82.17,55.58 82.36,55.58 82.7,55.24 82.88,55.24 83.01,55.37 83.01,55.55 82.67,55.89 82.67,56.08 82.8,56.2 82.98,56.2 83.33,55.86 83.51,55.86 83.64,55.99 83.64,56.17 83.29,56.52 83.29,56.7 83.42,56.83 83.61,56.83 83.95,56.49 84.13,56.49 84.43,56.78 84.43,61.55 84.25,61.73 80.48,65.5 80.48,70.66 81.7,71.87 81.7,79.56 81.05,80.21 81.05,83.77 80.2,84.62 80.2,86.47 81.08,87.35 U89.6
PR0_PRU1_GPIO5: length 57.6
  TOP w0.147: v1(83.32,60.45) 82.79,59.93 82.79,54.92 80.06,52.19 72.38,52.19 v1(71.23,51.05)
  BOTTOM w0.147: U89.7 80.93,87.85 79.79,86.7 79.79,84.62 80.74,83.67 80.74,80.06 81.37,79.42 81.37,72.01 80.16,70.79 80.16,65.37 84.02,61.5 84.02,57.93 83.81,57.71 83.52,57.71 83.32,57.92 v1(83.32,60.45) ; R252.2 70.85,50.67 v1(71.23,51.05)
PR0_PRU1_GPIO6: length 57.2
  TOP w0.147: v1(81.33,89.85) 82.93,88.25 84.82,88.25 85.77,87.3 85.77,85.06 86.5,84.33 86.5,81.07 89.03,78.54 89.03,74.45 87.86,73.29 87.86,71.63 88.68,70.81 88.68,65.84 87.17,64.33 87.17,63.07 83.44,59.35 83.44,54.73 79.99,51.27 77.44,51.27 77.34,51.18 76.41,51.18 76.08,51.51 72.46,51.51 71.98,51.02 R253.2
  BOTTOM w0.147: U89.11 v1(81.33,89.85)
PR0_PRU1_GPIO8: length 57.1
  BOTTOM w0.147: R254.2 74.39,50.27 73.81,50.85 73.81,51.93 75.66,53.78 76.2,53.78 76.33,53.66 76.33,53.52 76.46,53.39 76.64,53.39 76.77,53.52 76.77,53.66 76.9,53.78 77.09,53.78 77.21,53.66 77.21,53.52 77.34,53.39 77.53,53.39 77.66,53.52 77.66,53.66 77.79,53.78 77.97,53.78 78.1,53.66 78.1,53.52 78.23,53.39 78.41,53.39 78.54,53.52 78.54,53.66 78.67,53.78 79.64,53.78 82.64,56.79 82.64,57.52 82.51,57.65 82.2,57.65 82.08,57.78 82.08,57.96 82.2,58.09 82.51,58.09 82.64,58.22 82.64,58.4 82.51,58.53 82.2,58.53 82.08,58.66 82.08,58.85 82.2,58.98 82.51,58.98 82.64,59.11 82.64,59.29 82.51,59.42 82.2,59.42 82.08,59.55 82.08,59.73 82.2,59.86 82.51,59.86 82.64,59.99 82.64,60.17 82.51,60.3 82.2,60.3 82.08,60.43 82.08,60.61 82.2,60.74 82.51,60.74 82.64,60.87 82.64,61.06 82.51,61.19 82.2,61.19 82.08,61.31 82.08,61.5 82.2,61.63 82.51,61.63 82.64,61.76 82.64,62.42 79.83,65.23 79.83,70.93 81.05,72.14 81.05,79.29 80.42,79.91 80.42,83.56 78.96,85.03 78.96,89.35 79.95,90.35 U89.12
PR0_PRU1_GPIO9: length 51.4
  BOTTOM w0.147: R255.2 73.21,50.77 73.47,51.03 73.47,52.37 75.53,54.42 79.36,54.42 81.6,56.66 81.6,63 79.5,65.1 79.5,71.06 80.72,72.28 80.72,79.15 80.11,79.76 80.11,83.46 78.6,84.97 78.6,89.6 79.85,90.85 U89.13
PR0_PRU1_GPIO10: length 49.9
  TOP w0.147: v1(72.83,51.05) 73.2,50.68 R256.2
  BOTTOM w0.147: v1(72.83,51.05) 72.83,55.05 75.32,57.53 77.5,57.53 78.11,58.14 78.11,58.88 79.47,60.24 79.47,63.23 79.62,63.39 79.62,64.52 79.18,64.96 79.18,71.2 80.4,72.41 80.4,79.02 79.8,79.62 79.8,83.36 78.25,84.9 78.25,89.83 79.77,91.35 U89.14
PR0_PRU1_GPIO11: length 72.2
  TOP w0.147: v1(80.39,103.34) 80.61,103.11 80.61,102.79 80.43,102.62 80.19,102.62 79.98,102.82 79.72,102.82 79.54,102.64 79.54,97.8 80.19,97.15 80.19,88.86 80.89,88.16 80.89,87.71 80.41,87.22 80.41,86.53 81.45,85.49 81.45,81.9 82.07,81.28 82.07,77.95 83.32,76.7 84.02,76.7 84.17,76.55 84.17,76.17 83.56,75.56 82.45,75.56 81.89,74.99 81.89,70.92 81.15,70.17 81.15,65.61 82.93,63.82 82.93,61.3 82.14,60.51 82.14,55.11 79.84,52.81 71.26,52.81 70.01,51.56 v1(70.01,51.05)
  BOTTOM w0.147: U88.11 80.89,102.84 v1(80.39,103.34) ; R257.2 69.63,50.67 v1(70.01,51.05)
PR0_PRU1_GPIO12: length 71.9
  TOP w0.147: R258.2 69.54,50.83 69.32,51.05 69.32,51.44 70.99,53.11 79.74,53.11 81.82,55.2 81.82,60.68 82.58,61.45 82.58,63.68 80.81,65.45 80.81,70.31 81.54,71.04 81.54,75.14 82.37,75.97 83.01,75.97 83.16,76.12 83.16,76.33 82.81,76.67 82.63,76.67 82.47,76.5 82.28,76.5 82.15,76.63 82.15,76.82 82.32,76.98 82.32,77.16 81.67,77.82 81.67,79.62 81.54,79.75 81.33,79.75 81.2,79.88 81.2,80.07 81.33,80.19 81.54,80.19 81.67,80.32 81.67,81.23 81.1,81.8 81.1,85.39 79.88,86.61 79.88,96.81 79.19,97.5 79.19,102.92 80.06,103.79 80.85,103.79 v1(81.3,103.34)
  BOTTOM w0.147: U88.12 v1(81.3,103.34)
PR0_PRU1_GPIO13: length 71.8
  TOP w0.147: v1(68.79,51.05) 68.79,51.51 70.7,53.42 79.63,53.42 81.49,55.29 81.49,60.85 82.23,61.59 82.23,63.53 80.47,65.3 80.47,70.45 81.19,71.17 81.19,75.65 81.32,75.78 81.53,75.78 81.66,75.91 81.66,76.09 81.53,76.22 81.32,76.22 81.19,76.35 81.19,76.53 81.32,76.66 81.53,76.66 81.66,76.79 81.66,76.97 81.53,77.1 81.32,77.1 81.19,77.23 81.19,79.21 80.75,79.65 80.75,80.53 80.88,80.66 81.09,80.66 81.22,80.79 81.22,80.98 81.09,81.1 80.88,81.1 80.75,81.23 80.75,85.25 79.57,86.42 79.57,96.47 78.84,97.2 78.84,103.24 79.93,104.34 v1(80.39,104.34)
  BOTTOM w0.147: v1(68.79,51.05) 68.41,50.67 R259.2 ; U88.13 80.89,103.84 v1(80.39,104.34)
PR0_PRU1_GPIO14: length 72
  TOP w0.147: R260.2 70.76,50.83 70.62,50.97 70.62,51.33 71.79,52.5 79.95,52.5 82.47,55.01 82.47,60.34 83.28,61.16 83.28,63.97 81.48,65.77 81.48,70.03 82.24,70.79 82.24,74.85 82.48,75.09 83.62,75.09 84.61,76.08 84.61,76.71 84.24,77.08 83.52,77.08 82.46,78.13 82.46,81.34 81.8,82.01 81.8,85.6 80.84,86.55 80.84,87.11 81.24,87.5 81.24,88.34 80.52,89.06 80.52,97.39 79.89,98.01 79.89,101.39 81.19,102.68 81.77,102.68 82.05,102.97 82.05,103.58 v1(81.3,104.34)
  BOTTOM w0.147: U88.14 v1(81.3,104.34)
PR0_PRU1_GPIO15: length 72.5
  TOP w0.147: v1(80.39,105.34) 80.49,105.44 80.7,105.44 80.85,105.3 80.85,105.15 81.05,104.95 81.05,104.73 80.95,104.63 80.74,104.63 80.58,104.79 79.84,104.79 78.49,103.44 78.49,96.94 79.25,96.18 79.25,86.25 80.4,85.1 80.4,79.5 80.84,79.06 80.84,71.3 80.13,70.59 80.13,65.14 81.88,63.39 81.88,61.74 81.17,61.02 81.17,55.38 79.52,53.73 70.46,53.73 68.32,51.59 R261.2
  BOTTOM w0.147: U88.15 80.89,104.84 v1(80.39,105.34)
PR0_PRU1_GPIO16: length 72.1
  TOP w0.147: v1(67.83,51.05) 67.83,51.71 70.16,54.04 79.41,54.04 80.84,55.47 80.84,61.19 81.53,61.88 81.53,63.24 79.8,64.98 79.8,70.73 80.49,71.42 80.49,78.92 80.04,79.36 80.04,84.96 78.92,86.08 78.92,95.82 78.14,96.61 78.14,103.75 80.2,105.81 80.83,105.81 v1(81.3,105.34)
  BOTTOM w0.147: U88.16 v1(81.3,105.34) ; R262.2 67.19,50.87 67.37,51.05 v1(67.83,51.05)
PR0_PRU1_GPIO18: length 89.5
  TOP w0.147: v1(66.43,51.69) 66.43,51.65 R1652.2 ; v1(69.95,15.9) 69.08,15.9 68.94,16.04 R423.2
  L03_SIG1 w0.091: v1(69.95,15.9) 65.18,11.12 65.18,9.31 63.8,7.94 63.8,5.67 63.12,4.99 61.26,4.99 60.41,4.13 50.06,4.13 49.33,4.86 49.33,6.92 v1(48.64,7.61)
  L08_SIG2 w0.091: v1(66.43,51.69) 66.69,51.43 66.69,51.2 67.71,50.19 68.52,50.19 69.52,49.18 70.9,49.18 72.12,47.96 72.12,47.15 75.2,44.08 75.2,39.46 75.9,38.76 75.9,35.13 77.22,33.81 77.22,30.49 78.48,29.24 78.91,29.24 79.71,28.44 79.71,27.98 80.12,27.56 80.12,26.75 77.31,23.93 77.31,18.19 74.75,15.64 70.22,15.64 v1(69.95,15.9)
  BOTTOM w0.147: J15.70 47.84,6.81 v1(48.64,7.61)
PR0_PRU1_GPIO19: length 89.1
  TOP w0.147: v1(72.05,16.1) 71.91,16.24 R420.2 ; R1653.2 v1(65.2,51.69)
  L03_SIG1 w0.091: v1(72.05,16.1) 71.04,16.1 66.59,11.66 66.59,9.82 65.64,8.86 65.64,4.57 64.8,3.73 48.87,3.73 48.21,4.38 48.21,4.4 v1(47.04,5.58)
  L08_SIG2 w0.091: v1(65.2,51.69) 66.12,50.77 66.84,50.77 67.66,49.94 68.4,49.94 69.39,48.95 70.51,48.95 71.69,47.78 71.69,46.2 73.6,44.28 74.41,44.28 74.97,43.72 74.97,39.3 75.66,38.61 75.66,35.03 76.82,33.86 76.82,29.2 78.25,27.78 79.45,27.78 79.79,27.44 79.79,26.8 76.4,23.41 76.4,17.67 74.83,16.1 v1(72.05,16.1)
  BOTTOM w0.147: v1(47.04,5.58) 47.49,5.12 47.49,4.37 47.04,3.92 J15.68
PR0_PRU1_REF_CLK: length 101.1
  TOP w0.147: J8.28 v1(73.27,93.04) ; R274.2 v1(28.89,37.39)
  L08_SIG2 w0.091: v1(28.89,37.39) 27.4,38.89 27.4,46.51 25.88,48.03 25.88,60.78 26.39,61.3 28.7,61.3 29.57,62.17 31.06,62.17 31.74,62.84 40.24,62.84 42.33,64.94 48.79,64.94 49.37,64.37 50.53,64.37 52.03,62.86 58.19,62.86 59.23,63.9 62.02,63.9 62.65,64.53 62.65,66.23 61.44,67.44 61.44,75.06 64.98,78.61 64.98,85.44 69.82,90.28 69.82,91.13 71.73,93.04 v1(73.27,93.04)
QSPI_CLK: length 34.4
  TOP w0.147: U18.6 30.27,55.11 30.16,55.21 R89.1 v1(29.66,54.6)
  L08_SIG2 w0.091: v1(29.66,54.6) 32.73,54.6 34.25,53.08 34.25,51.78 39.23,46.81 39.34,46.81 39.42,46.89 39.42,47 34.81,51.61 34.81,51.78 34.89,51.86 35.01,51.86 40.53,46.33 41.3,46.33 v1(41.73,46.76)
  BOTTOM w0.147: U80.41 41.23,46.26 v1(41.73,46.76)
QSPI_CS1: length 28.1
  TOP w0.147: U18.1 40.11,52.57 R86.2 v1(40.67,51.84)
  L03_SIG1 w0.091: v1(46.74,34.95) 46.4,34.61 43.13,34.61 42.05,35.69 42.05,36.34 42.4,36.69 42.4,47.27 40.67,49 v1(40.67,51.84)
  BOTTOM w0.147: R99.1 TP46.1 47.06,34.74 46.84,34.95 v1(46.74,34.95)
QSPI_D0: length 31.6
  TOP w0.147: R439.2 R1667.1 v1(27.79,58.41)
  L08_SIG2 w0.091: v1(27.79,58.41) 28.58,57.61 37.46,57.61 38.17,56.9 38.17,52.24 38.25,52.16 38.37,52.16 38.45,52.24 38.45,54.53 38.54,54.62 38.65,54.62 38.73,54.54 38.73,48.75 v1(40.73,46.76)
  BOTTOM w0.147: v1(40.73,46.76) 40.23,46.26 U80.39
QSPI_D1: length 31.9
  TOP w0.147: v1(42.71,52.99) 42.83,53.11 R1668.1 R440.2
  L08_SIG2 w0.091: v1(42.71,52.99) 42.71,54.64 42.62,54.73 41.31,54.73 41.22,54.64 41.22,54.47 41.3,54.39 42.13,54.39 42.21,54.31 42.21,54.2 42.13,54.12 41.3,54.12 41.22,54.04 41.22,53.92 41.3,53.84 42.13,53.84 42.21,53.76 42.21,53.65 42.13,53.57 41.3,53.57 41.22,53.49 41.22,53.38 41.3,53.3 42.13,53.3 42.21,53.21 42.21,53.1 42.13,53.02 41.3,53.02 41.22,52.94 41.22,52.83 41.3,52.75 42.13,52.75 42.21,52.67 42.21,52.55 42.13,52.47 41.3,52.47 41.22,52.39 41.22,48.44 42.61,47.05 42.61,42.49 42.07,41.95 39.83,41.95 39.28,42.51 v1(39.28,44.91)
  BOTTOM w0.147: U80.38 v1(39.28,44.91)
QSPI_D2: length 32.2
  TOP w0.147: R441.2 R84.2 42.83,55.58 v1(42.29,56.12)
  L08_SIG2 w0.091: v1(42.29,56.12) 40.81,56.12 39.29,54.61 39.29,49.78 39.37,49.7 39.49,49.7 39.57,49.78 39.57,53.78 39.65,53.86 39.76,53.86 39.84,53.78 39.84,49.29 42.22,46.91 42.22,45.28 41.89,44.94 40.49,44.94 39.95,45.48 38.75,45.48 38.17,44.9 v1(38.17,43.62)
  BOTTOM w0.147: U80.36 38.47,43.32 v1(38.17,43.62)
QSPI_D3: length 32.7
  TOP w0.147: R442.2 R85.2 v1(27.56,54.73)
  L08_SIG2 w0.091: v1(37.21,42.79) 37.5,43.08 37.5,46.58 33.19,50.9 33.19,51.02 33.27,51.1 33.42,51.1 37,47.51 37.12,47.51 37.2,47.59 37.2,47.71 30.95,53.96 28.33,53.96 v1(27.56,54.73)
  BOTTOM w0.147: v1(37.21,42.79) 37.67,42.32 U80.34
R_LED2_0: length 6.6
  BOTTOM w0.147: J7.11 109.27,77.15 107.54,78.88 105.96,78.88 105.6,79.24 R216.1
RBIAS2: length 5.1
  BOTTOM w0.147: U35.12 94.16,65.84 94.74,65.27 TP63.1 R215.1
RESETZ: length 45.8
  L03_SIG1 w0.091: v1(54.33,52.17) 48.6,57.9 48.6,63.46 49.19,64.05 49.19,71.45 51.03,73.3 51.03,78.59 50.23,79.39 50.23,84.4 52.36,86.52 v1(52.36,89.94)
  BOTTOM w0.147: v1(54.33,52.17) 53.91,51.74 R185.1 ; U76.2 53.06,90.02 R428.2 v1(52.36,89.94)
RESETZ_HSEC: length 8.4
  TOP w0.147: R419.2 v1(67.93,9.64)
  BOTTOM w0.147: J15.120 67.84,4.91 67.21,5.54 67.21,8.92 v1(67.93,9.64)
RJ45_ETH0_D0_N: length 9.7
  BOTTOM w0.108: U35.2 93.32,70.84 93.43,70.95 95.7,70.95 96.74,72 98.33,72 99.66,73.33 99.66,74.02 J7.10
RJ45_ETH0_D0_P: length 9.7
  BOTTOM w0.108: J7.9 98.86,73.98 99.2,73.98 99.37,73.82 99.37,73.45 98.21,72.29 96.62,72.29 95.58,71.24 93.43,71.24 93.32,71.34 U35.1
RJ45_ETH0_D1_N: length 9.4
  BOTTOM w0.108: U35.5 93.32,69.34 93.43,69.45 98.55,69.45 99.66,70.56 99.66,71.48 J7.8
RJ45_ETH0_D1_P: length 9.4
  BOTTOM w0.108: U35.4 93.32,69.84 93.43,69.74 98.43,69.74 99.37,70.68 99.37,71.28 99.2,71.44 98.86,71.44 J7.7
RJ45_ETH0_D2_N: length 9.8
  BOTTOM w0.108: U35.8 93.32,67.84 93.43,67.95 95.99,67.95 96.93,67.01 98.71,67.01 99.66,67.96 99.66,68.94 J7.6
RJ45_ETH0_D2_P: length 9.8
  BOTTOM w0.108: J7.5 98.86,68.9 99.2,68.9 99.37,68.74 99.37,68.08 98.59,67.3 97.05,67.3 96.11,68.24 93.43,68.24 93.32,68.34 U35.7
RJ45_ETH0_D3_N: length 10.1
  BOTTOM w0.108: U35.11 93.32,66.34 93.43,66.45 94.57,66.45 96.52,64.5 97.28,64.5 98.39,64.5 98.39,64.5 98.49,64.5 99.66,65.67 99.66,66.4 J7.4
RJ45_ETH0_D3_P: length 10.1
  BOTTOM w0.108: J7.3 98.86,66.36 99.2,66.36 99.37,66.2 99.37,65.79 98.37,64.79 98.27,64.79 98.27,64.79 97.4,64.79 97.4,64.79 96.64,64.79 94.69,66.74 93.43,66.74 93.32,66.84 U35.10
RSVD_T4: length 5.9
  TOP w0.147: U1.T4 v1(55.38,34.43)
  BOTTOM w0.114: 57.38,33.37 57.38,33.86 57.21,34.03 55.78,34.03
  BOTTOM w0.147: R82.1 58.11,31.62 57.38,32.34 57.38,33.37 ; 55.78,34.03 v1(55.38,34.43)
RSVD_U1: length 3.9
  TOP w0.147: R186.1 52.03,31.25 52.83,32.04 52.83,33.48 U1.U1
RSVD_U3: length 4.6
  TOP w0.147: U1.U3 54.59,33.64 54.59,33 54.49,32.9 54.49,32.29 53.61,31.41 TP59.1
RSVD_V2: length 5.8
  TOP w0.147: TP60.1 52.7,28.82 52.72,28.83 52.72,31.13 54.18,32.59 U1.V2
SAFETY_ERRORN: length 89.5
  TOP w0.147: Q20.1 76.62,30.58 77.06,30.14 77.64,30.14 78.22,29.56 78.22,28.3 v1(79.2,27.32) ; U1.D4 v1(55.38,44.83)
  L08_SIG2 w0.091: v1(79.2,27.32) 78.24,27.32 76.4,29.16 76.4,33.94 75.41,34.93 75.41,38.36 74.74,39.03 74.74,43.57 74.3,44.02 73.43,44.02 71.29,46.16 71.29,47.46 70.7,48.05 69.94,48.05 68.27,49.73 67.5,49.73 66.84,50.39 65.71,50.39 64.41,51.7 64.41,52.25 63.54,53.11 62.09,53.11 60.83,51.85 60.83,48.26 59.77,47.2 59.77,45.47 59.54,45.24 59.24,45.24 58.97,44.97 58.97,44.67 58.74,44.44 55.83,44.44 55.44,44.83 v1(55.38,44.83)
  BOTTOM w0.114: v1(55.38,44.83) 54.98,45.23 52.8,45.23
  BOTTOM w0.147: 52.8,45.23 52.52,45.23 51.86,45.89 TP56.1 ; R435.2 106.97,27.31 106.96,27.32 v1(79.2,27.32)
SOC_BOOTMODE0: length 83.8
  L08_SIG2 w0.091: v1(67.81,85.98) 67.2,85.98 65.73,84.51 65.73,80.83 66.36,80.2 66.36,77.29 65.32,76.26 65.32,64.54 63.49,62.7 61.11,62.7 60.63,63.19 59.28,63.19 56.78,60.68 53.44,60.68 50.33,63.79 49.23,63.79 49.04,63.6 43.02,63.6 42.86,63.44 41.53,62.11 41.53,58.49 43.03,56.99 43.03,55.4 43.42,55.02 43.42,52.46 42.04,51.08 42.04,48.59 44.85,45.79 45.68,45.79 46.06,45.41 v1(46.06,44.57)
  BOTTOM w0.147: v1(67.81,85.98) 67.49,86.3 U48.15 ; v1(46.06,44.57) 47.35,43.29 47.35,40.66 45.65,38.96 45.65,36.77 46.29,36.13 R119.2
SOC_BOOTMODE1: length 82.7
  L08_SIG2 w0.091: v1(45.37,45.26) 44.42,45.26 42.99,46.69 42.99,47.2 41.77,48.42 41.77,51.2 43.14,52.57 43.14,54.9 42.76,55.28 42.76,56.87 41.25,58.37 41.25,62.23 42.9,63.88 48.82,63.88 49.03,64.09 50.42,64.09 53.56,60.95 56.67,60.95 59.17,63.46 60.74,63.46 61.22,62.97 63.38,62.97 65.02,64.61 65.02,77.95 65.25,78.19 65.25,84.47 v1(67.81,87.02)
  BOTTOM w0.147: U48.14 67.49,86.7 v1(67.81,87.02) ; v1(45.37,45.26) 46.43,45.26 47.68,44.02 47.68,40.58 46.82,39.72 R122.2
SOC_BOOTMODE2: length 48
  TOP w0.147: R150.2 60.54,52.74 v1(60.54,53.61)
  L03_SIG1 w0.091: v1(60.54,53.61) 58.58,55.58 58.58,64.92 60.86,67.2 60.86,69.82 60.39,70.29 59.11,70.29 58.34,71.07 58.34,78.73 60.33,80.72 60.33,82.43 61.85,83.95 61.85,88.58 v1(62.86,89.59)
  BOTTOM w0.147: U48.13 66.75,88.2 65.37,89.59 v1(62.86,89.59)
SOC_BOOTMODE3: length 50
  L03_SIG1 w0.091: v1(61.59,89.59) 61.59,84.06 60.07,82.54 60.07,80.83 58.06,78.83 58.06,70.97 59,70.03 60.28,70.03 60.59,69.73 60.59,67.24 58.34,64.99 58.34,54.65 v1(59.37,53.61)
  BOTTOM w0.147: R151.2 60.72,51.64 60.72,52.27 v1(59.37,53.61) ; U48.12 66.15,87.88 65.04,89 62.18,89 v1(61.59,89.59)
SOC_CLK_IN: length 1.4
  TOP w0.147: U43.4 R176.1
SOC_CLK_XTAL_IN: length 4.3
  TOP w0.147: Y1.1 47.22,30.99 47.39,30.82 C184.1 49.75,30.82 50.01,31.08 R178.1
SOC_CLK_XTAL_OUT: length 5.8
  TOP w0.147: Y1.3 46.02,34.28 46.15,34.4 47.74,34.4 48.25,33.89 C185.1 49.59,33.89 49.94,33.54 R179.1
SOC_I2C0_SCL: length 35.6
  TOP w0.147: R135.1 v1(62.62,51.73)
  BOTTOM w0.147: R159.2 48.48,70.26 U26.4 45.6,70.26 45.18,69.85 45.18,67.49 46.13,66.54 47.34,66.54 47.97,65.9 47.97,59.41 52.55,54.84 60.22,54.84 61.31,53.74 61.31,53.04 v1(62.62,51.73)
SOC_I2C0_SDA: length 30.8
  BOTTOM w0.147: R136.1 63.91,52.53 61.07,55.37 52.71,55.37 48.43,59.65 48.43,62.86 49.18,63.61 R158.2 U26.7
SOC_I2C2_SCL: length 119.4
  TOP w0.147: v1(66.54,76.31) 66.09,76.31 65.93,76.47 58.5,76.47 56.96,74.93 v1(56.96,74.37) ; R156.2 v1(54.41,49.14) ; U1.C7 v1(57.78,45.63) ; U46.3 v1(49.14,77.46)
  L03_SIG1 w0.091: v1(56.96,74.37) 56.44,73.86 56.44,73.61 55.27,72.44 52.23,72.44 50.46,70.67 50.46,65.08 49.52,64.14 49.52,62.45 49.97,62 v1(49.97,61.46) 49.97,57.58 54.79,52.76 54.79,49.52 v1(54.41,49.14)
  L08_SIG2 w0.091: v1(49.14,77.46) 49.93,77.46 52.54,74.86 56.47,74.86 v1(56.96,74.37) ; v1(57.78,45.63) 57.37,46.04 56.81,46.04 56.59,46.26 56.59,47.58 55.82,48.35 55.52,48.35 54.74,49.14 v1(54.41,49.14) ; v1(89.75,61.46) 89.75,60.48 85.91,56.63 81.44,56.63 80.23,55.43 79.08,55.43 78.3,54.65 71.79,54.65 70.45,55.98 69.42,55.98 69,56.41 67.6,56.41 66.85,57.16 66.85,68.65 67.03,68.82 67.03,75.83 v1(66.54,76.31)
  BOTTOM w0.147: U59.15 v1(66.54,76.31) ; U60.29 56.46,73.87 v1(56.96,74.37) ; v1(89.75,61.46) 89.75,60.55 89.09,59.89 U13.5 89.09,58.75 89.44,58.4 89.77,58.4 90.99,59.62 U12.5 ; U27.8 v1(49.97,61.46)
SOC_I2C2_SDA: length 117.5
  TOP w0.147: R157.2 55.55,49.31 v1(55.73,49.14) ; U46.2 v1(49.14,76.19) ; v1(68.07,76.31) 67.61,76.77 58.12,76.77 56.47,75.12 56.47,73.93 v1(56.96,73.44) ; U1.B7 v1(57.78,46.43)
  L03_SIG1 w0.091: v1(55.73,49.14) 55.52,49.35 55.52,50.25 55.8,50.53 55.8,52.47 50.55,57.72 50.55,62.14 v1(49.97,62.73) 49.97,63.99 50.73,64.75 50.73,70.42 52.4,72.09 55.6,72.09 v1(56.96,73.44)
  L08_SIG2 w0.091: v1(55.73,49.14) 56.01,49.14 56.88,48.27 57.29,48.27 58.17,47.39 58.17,47.07 57.78,46.68 v1(57.78,46.43) ; v1(49.14,76.19) 50.71,76.19 52.38,74.52 55.88,74.52 v1(56.96,73.44) ; v1(87.26,61.42) 87.74,60.94 87.74,60 85.66,57.93 78.93,57.93 77.33,56.33 72.04,56.33 71.49,55.78 71.2,55.78 70.79,56.19 70.79,56.67 69.8,57.66 67.67,57.66 67.36,57.97 67.36,68.16 67.56,68.36 67.56,75.8 v1(68.07,76.31)
  BOTTOM w0.147: U27.7 v1(49.97,62.73) ; U60.30 v1(56.96,73.44) ; v1(87.26,61.42) 87.87,60.81 88.37,60.81 88.59,60.58 U13.4 88.59,58.45 89.02,58.03 89.87,58.03 90.96,59.12 U12.4 ; U59.2 v1(68.07,76.31)
SOC_INTN: length 40.2
  TOP w0.147: v1(48.64,64.31) 47.99,64.96 U20.2
  L03_SIG1 w0.091: v1(52.06,95.24) 50.19,95.24 48.67,93.72 48.67,92.13 52.04,88.76 52.04,86.61 49.92,84.49 49.92,82.07 48.53,80.68 48.53,64.79 48.64,64.69 v1(48.64,64.31)
  BOTTOM w0.147: U76.5 v1(52.06,95.24)
SOC_MMC0_CLK: length 13.6
  TOP w0.147: U1.B6 v1(56.98,46.43) ; RA2.5 50.92,50.22 50.92,50.45 v1(51.03,50.55) 50.92,50.66 TP49.1
  L08_SIG2 w0.091: v1(56.98,46.43) 57.37,46.82 57.37,47.39 56.13,48.63 55.63,48.63 54.44,49.82 54.33,49.82 54.17,49.66 54.05,49.66 53.97,49.74 53.97,49.85 54.13,50.01 54.13,50.13 54.05,50.21 53.94,50.21 53.78,50.05 53.66,50.05 53.58,50.13 53.58,50.24 53.75,50.4 53.75,50.52 53.23,51.03 52.21,51.03 51.73,50.55 v1(51.03,50.55)
  BOTTOM w0.147: v1(51.03,50.55) 50.92,50.66 50.92,50.77 RA3.5
SOC_MMC0_CMD: length 12.8
  TOP w0.147: RA4.6 46.35,50.28 v1(46.6,50.53) ; U1.A4 v1(55.38,47.23)
  L08_SIG2 w0.091: v1(55.38,47.23) 55.38,47.33 54.62,48.09 52.25,48.09 51.41,48.93 51.16,48.93 49.73,50.36 49.73,50.55 49.32,50.96 47.03,50.96 v1(46.6,50.53)
  BOTTOM w0.147: RA5.6 46.3,50.84 v1(46.6,50.53)
SOC_MMC0_DAT0: length 12.5
  TOP w0.147: U1.B5 v1(56.18,46.43) ; v1(50.16,50.53) 49.9,50.28 RA2.6
  L08_SIG2 w0.091: v1(50.16,50.53) 50.16,50.43 50.33,50.26 50.89,49.7 51,49.7 51.05,49.76 51.17,49.76 51.25,49.68 51.25,49.56 51.19,49.51 51.19,49.4 51.34,49.25 51.56,49.25 51.76,49.45 51.87,49.45 51.95,49.37 51.95,49.26 51.81,49.11 51.81,49 51.9,48.9 52.09,48.9 52.5,49.31 53.24,49.31 53.46,49.08 53.46,48.89 53.37,48.79 53.18,48.79 53.09,48.7 53.09,48.5 53.19,48.4 54.7,48.4 55.37,47.73 55.52,47.73 55.79,47.46 55.79,46.82 v1(56.18,46.43)
  BOTTOM w0.147: RA3.6 49.85,50.84 v1(50.16,50.53)
SOC_MMC0_DAT1: length 12.8
  TOP w0.147: v1(49.14,50.53) 49.4,50.28 49.4,49.84 ; U1.B4 v1(55.38,46.43)
  L08_SIG2 w0.091: v1(49.14,50.53) 49.14,50.16 49.22,50.08 49.56,50.08 49.64,50 49.64,49.89 49.56,49.81 49.22,49.81 49.14,49.73 49.14,49.44 49.28,49.31 49.67,49.31 49.75,49.23 49.75,48.85 49.92,48.69 50.07,48.69 50.15,48.77 50.15,49.23 50.23,49.31 50.37,49.31 51.02,48.66 51.28,48.66 52.12,47.82 54.11,47.82 54.31,47.62 54.74,47.62 54.99,47.37 54.99,46.83 v1(55.38,46.43)
  BOTTOM w0.147: v1(49.14,50.53) 49.35,50.74 RA3.7
SOC_MMC0_DAT2: length 13
  TOP w0.147: v1(48.26,50.53) 48.26,50.35 RA2.8 ; U1.A3 v1(54.58,47.23)
  L08_SIG2 w0.091: v1(54.58,47.23) 54.33,47.23 53.94,47.62 52.82,47.62 52.68,47.47 50.32,47.47 49.69,48.11 49.69,48.53 49.23,48.99 48.56,48.99 48.56,48.99 48.33,48.99 48.23,49.08 48.23,49.25 48.26,49.27 48.26,49.28 48.34,49.36 48.71,49.36 48.79,49.44 48.79,49.56 48.71,49.64 48.34,49.64 48.26,49.72 48.26,49.83 48.34,49.91 48.71,49.91 48.79,49.99 48.79,50.11 48.71,50.19 48.34,50.19 48.26,50.27 v1(48.26,50.53)
  BOTTOM w0.147: RA3.8 48.26,50.74 v1(48.26,50.53)
SOC_MMC0_DAT3: length 12.9
  TOP w0.147: RA4.5 47.37,50.22 v1(47.37,50.53) ; U1.A2 v1(53.78,47.23)
  L08_SIG2 w0.091: v1(53.78,47.23) 53.39,46.84 51.61,46.84 51.42,47.03 50.3,47.03 49.64,47.69 49.1,47.69 48.72,48.07 48.72,48.45 48.45,48.72 47.56,48.72 47.37,48.91 47.37,49.22 47.45,49.3 47.73,49.3 47.81,49.38 47.81,49.5 47.73,49.58 47.45,49.58 47.37,49.66 47.37,49.77 47.45,49.85 47.73,49.85 47.81,49.93 47.81,50.05 47.73,50.13 47.45,50.13 47.37,50.21 v1(47.37,50.53)
  BOTTOM w0.147: RA5.5 47.37,50.77 v1(47.37,50.53)
SOC_MMC0_SDCD: length 15.4
  TOP w0.147: 45.85,49.84 45.85,50.28 v1(45.59,50.53) ; U1.A5 v1(56.18,47.23)
  L08_SIG2 w0.091: v1(45.59,50.53) 46.29,51.23 50.06,51.23 50.6,50.69 50.6,50.38 50.85,50.13 51.63,50.13 51.82,49.94 52.17,49.94 52.42,50.19 52.77,50.19 53.84,49.12 53.84,48.86 54,48.7 54.79,48.7 55.41,48.08 55.7,48.08 56.18,47.6 v1(56.18,47.23)
  BOTTOM w0.147: RA5.7 45.8,50.74 v1(45.59,50.53)
SOC_MMC0_WP: length 17.5
  TOP w0.147: U1.C6 v1(56.98,45.63) ; v1(44.7,50.53) 44.7,50.35 RA4.8
  L08_SIG2 w0.091: v1(44.7,50.53) 44.7,49.63 46.74,47.59 48.75,47.59 49.64,46.7 51.29,46.7 52.75,45.24 56.59,45.24 v1(56.98,45.63)
  BOTTOM w0.147: RA5.8 44.7,50.74 v1(44.7,50.53)
SOC_OSPI0_CLK: length 18.7
  TOP w0.147: v1(47.44,38.52) 48,37.96 48.89,37.96 49.2,38.27 R87.1
  L03_SIG1 w0.091: v1(43.67,43.82) 43.93,44.08 46.64,44.08 48.19,42.53 48.19,42.42 48.11,42.34 47.93,42.34 46.42,43.85 46.3,43.85 46.22,43.77 46.22,43.65 48.35,41.53 48.65,41.53 49,41.18 49,39.57 48.46,39.04 48.25,39.04 47.74,38.52 v1(47.44,38.52)
  BOTTOM w0.147: U80.2 v1(43.67,43.82)
SOC_OSPI0_CSN0: length 3.5
  TOP w0.147: R98.2 51.63,37.13 52.33,36.43 U1.P1
SOC_OSPI0_CSN1: length 5.9
  TOP w0.147: U1.R3 v1(54.58,35.23)
  BOTTOM w0.114: 53.54,35.63 54.01,35.63
  BOTTOM w0.147: 54.01,35.63 54.18,35.63 v1(54.58,35.23) ; R99.2 50.18,33.89 50.94,34.66 52.07,34.66 53.04,35.63 53.54,35.63
SOC_OSPI0_D0: length 17.6
  L03_SIG1 w0.091: v1(44.79,42.82) 44.27,42.29 44.27,40.95 44.52,40.71 44.52,40.54 44.34,40.36 44.2,40.36 44.06,40.5 43.52,40.5 43.11,40.09 43.11,36.62 43.61,36.12 44.62,36.12 v1(45.06,35.68)
  BOTTOM w0.147: U80.3 44.29,43.32 v1(44.79,42.82) ; R90.1 48.51,36.26 48.38,36.13 R119.1 47.8,35.71 47.6,35.51 46.62,35.51 46.28,35.17 45.56,35.17 v1(45.06,35.68)
